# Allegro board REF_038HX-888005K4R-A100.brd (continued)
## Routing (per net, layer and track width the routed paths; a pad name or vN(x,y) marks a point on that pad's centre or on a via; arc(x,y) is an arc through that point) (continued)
N24642488: length 2.2
  BOTTOM w0.231: R53.2 93.8,160.77 94.63,161.6 K24.6
N24642490: length 2.2
  BOTTOM w0.231: R54.1 97.66,160.72 96.83,161.55 K24.5
N24780353: length 2.4
  BOTTOM w0.231: R131.1 K12.4
N24780370: length 2.4
  BOTTOM w0.231: R132.1 K12.5
N24787993: length 2.3
  BOTTOM w0.889: 94.1,260.04 CA21.1
  BOTTOM w1.524: K34.5 94.1,260.04
N24789529: length 7.4
  BOTTOM w0.889: 61.48,219.4 CA23.1
  BOTTOM w1.524: K36.8 K36.5 61.48,219.4
N24789779: length 2.3
  BOTTOM w0.889: 61.48,280.36 CA24.1
  BOTTOM w1.524: K37.5 61.48,280.36
N24793751: length 3.4
  TOP w0.231: RT3.1 RT5.1 UT1.3
N24793759: length 16.2
  TOP w0.231: UT1.4 149.59,241.68 v1(148.57,240.67)
  BOTTOM w0.231: v1(148.57,240.67) 152.89,240.67 157.11,244.89 159.52,244.89 v1(160.13,245.49)
N24793795: length 2.1
  TOP w0.231: UT1.6 RT7.2
N24793797: length 2.1
  TOP w0.231: UT1.5 RT8.2
N25306310: length 2.2
  BOTTOM w0.231: R102.2 93.8,185.29 94.63,184.46 K22.3
N25306320: length 2.2
  BOTTOM w0.231: K22.4 96.83,184.5 97.66,185.33 R103.1
N25306354: length 2.2
  BOTTOM w0.231: R104.2 83.17,195.33 82.34,194.5 K27.3
N25306364: length 2.2
  BOTTOM w0.231: K27.4 82.39,192.3 83.22,191.47 R105.1
N25330426: length 2.3
  BOTTOM w0.889: 61.08,239.72 CA29.1
  BOTTOM w1.524: K42.5 61.08,239.72
N25334489: length 2.3
  BOTTOM w0.889: 61.08,260.04 CA26.1
  BOTTOM w1.524: K39.5 61.08,260.04
N25337760: length 2.3
  BOTTOM w0.889: 77.79,260.04 CA34.1
  BOTTOM w1.524: K31.5 77.79,260.04
N25339188: length 2.3
  BOTTOM w0.889: 77.79,239.72 CA27.1
  BOTTOM w1.524: K40.5 77.79,239.72
N25362248: length 2.1
  BOTTOM w0.508: K33.2 R82.1
N25362250: length 2.1
  BOTTOM w0.508: K33.4 R117.1
N25362465: length 2.2
  BOTTOM w0.231: K11.3 144.88,272.51 145.71,271.68 R39.2
N25362471: length 2.2
  BOTTOM w0.231: R40.1 141.85,271.64 142.68,272.47 K11.4
N25362509: length 2.2
  BOTTOM w0.231: R38.1 141.85,265.52 142.68,264.69 K8.5
N25362552: length 2.2
  BOTTOM w0.231: K8.3 144.88,256 145.71,255.17 R35.2
N25362554: length 2.2
  BOTTOM w0.231: R36.1 141.85,255.13 142.68,255.96 K8.4
N25362556: length 2.2
  BOTTOM w0.231: K8.6 144.88,264.64 145.71,265.47 R37.2
N25362573: length 2.2
  BOTTOM w0.231: K11.6 144.88,281.15 145.71,281.98 R41.2
N25362575: length 2.2
  BOTTOM w0.231: R42.1 141.85,282.03 142.68,281.2 K11.5
N25362658: length 2.2
  BOTTOM w0.231: K3.5 173.16,297.71 172.33,298.54 R18.1
N25362663: length 2.2
  BOTTOM w0.231: R17.2 176.19,298.49 175.36,297.66 K3.6
N25362668: length 2.2
  BOTTOM w0.231: R16.1 172.33,288.15 173.16,288.98 K3.4
N25362670: length 2.2
  BOTTOM w0.231: R15.2 176.19,288.19 175.36,289.02 K3.3
N25362705: length 2.2
  BOTTOM w0.231: K1.5 173.16,281.2 172.33,282.03 R10.1
N25362707: length 2.2
  BOTTOM w0.231: K1.6 175.36,281.15 176.19,281.98 R9.2
N25362709: length 2.2
  BOTTOM w0.231: R8.1 172.33,271.64 173.16,272.47 K1.4
N25362711: length 2.2
  BOTTOM w0.231: K1.3 175.36,272.51 176.19,271.68 R7.2
N25362734: length 2.2
  BOTTOM w0.231: R11.2 176.19,255.17 175.36,256 K2.3
N25362739: length 2.2
  BOTTOM w0.231: K2.4 173.16,255.96 172.33,255.13 R12.1
N25362741: length 2.2
  BOTTOM w0.231: K4.5 157.92,297.71 157.09,298.54 R22.1
N25362761: length 2.2
  BOTTOM w0.231: K4.3 160.12,289.02 160.95,288.19 R19.2
N25362763: length 2.2
  BOTTOM w0.231: K4.4 157.92,288.98 157.09,288.15 R20.1
N25362765: length 2.2
  BOTTOM w0.231: R21.2 160.95,298.49 160.12,297.66 K4.6
N25362815: length 2.2
  BOTTOM w0.231: R26.1 157.09,265.52 157.92,264.69 K5.5
N25362863: length 2.2
  BOTTOM w0.231: K5.3 160.12,256 160.95,255.17 R23.2
N25362865: length 2.2
  BOTTOM w0.231: K5.4 157.92,255.96 157.09,255.13 R24.1
N25362867: length 2.2
  BOTTOM w0.231: R25.2 160.95,265.47 160.12,264.64 K5.6
N25363066: length 2.2
  BOTTOM w0.231: K16.3 129.64,256 130.47,255.17 R67.2
N25363068: length 2.2
  BOTTOM w0.231: R68.1 126.61,255.13 127.44,255.96 K16.4
N25363070: length 2.2
  BOTTOM w0.231: K16.5 127.44,264.69 126.61,265.52 R70.1
N25363072: length 2.2
  BOTTOM w0.231: K16.6 129.64,264.64 130.47,265.47 R69.2
N25363098: length 2.2
  BOTTOM w0.231: K17.3 129.64,272.51 130.47,271.68 R71.2
N25363100: length 2.2
  BOTTOM w0.231: R72.1 126.61,271.64 127.44,272.47 K17.4
N25363118: length 2.2
  BOTTOM w0.231: K17.5 127.44,281.2 126.61,282.03 R74.1
N25363120: length 2.2
  BOTTOM w0.231: R73.2 130.47,281.98 129.64,281.15 K17.6
N25363130: length 2.2
  BOTTOM w0.231: R75.2 130.47,288.19 129.64,289.02 K21.3
N25363148: length 2.2
  BOTTOM w0.231: R76.1 126.61,288.15 127.44,288.98 K21.4
N25363150: length 2.2
  BOTTOM w0.231: R78.1 126.61,298.54 127.44,297.71 K21.5
N25363152: length 2.2
  BOTTOM w0.231: K21.6 129.64,297.66 130.47,298.49 R77.2
N25363178: length 2.2
  BOTTOM w0.231: K29.3 114.4,272.51 115.23,271.68 R79.2
N25363180: length 2.2
  BOTTOM w0.231: K29.4 112.2,272.47 111.37,271.64 R80.1
N25363198: length 2.2
  BOTTOM w0.231: R14.1 172.33,265.52 173.16,264.69 K2.5
N25363200: length 2.2
  BOTTOM w0.231: R13.2 176.19,265.47 175.36,264.64 K2.6
N25363358: length 2.2
  BOTTOM w0.231: R43.2 115.23,281.98 114.4,281.15 K29.6
N25363360: length 2.2
  BOTTOM w0.231: R44.1 111.37,282.03 112.2,281.2 K29.5
N25363376: length 2.2
  BOTTOM w0.231: R63.2 115.23,288.19 114.4,289.02 K30.3
N25363378: length 2.2
  BOTTOM w0.231: R64.1 111.37,288.15 112.2,288.98 K30.4
N25363404: length 2.2
  BOTTOM w0.231: K30.5 112.2,297.71 111.37,298.54 R101.1
N25363406: length 2.2
  BOTTOM w0.231: K30.6 114.4,297.66 115.23,298.49 R100.2
N25363469: length 2.2
  BOTTOM w0.231: K6.5 157.92,281.2 157.09,282.03 R30.1
N25363533: length 2.2
  BOTTOM w0.231: R27.2 160.95,271.68 160.12,272.51 K6.3
N25363535: length 2.2
  BOTTOM w0.231: R28.1 157.09,271.64 157.92,272.47 K6.4
N25363537: length 2.2
  BOTTOM w0.231: K6.6 160.12,281.15 160.95,281.98 R29.2
N25363539: length 2.2
  BOTTOM w0.231: R34.1 141.85,298.54 142.68,297.71 K7.5
N25363555: length 2.2
  BOTTOM w0.231: R31.2 145.71,288.19 144.88,289.02 K7.3
N25363557: length 2.2
  BOTTOM w0.231: K7.4 142.68,288.98 141.85,288.15 R32.1
N25363559: length 2.2
  BOTTOM w0.231: R33.2 145.71,298.49 144.88,297.66 K7.6
N25363681: length 5.3
  BOTTOM w0.231: K18.4 100.66,244.92 100.25,245.33 R6.2 R5.1
N25363685: length 5.3
  BOTTOM w0.231: R133.1 R6.1 100.19,246.33 100.66,246.8 K18.5
N25363701: length 3.5
  BOTTOM w0.231: Y1.1 96.65,248.49 C5.1 R133.2
N25363703: length 6.1
  BOTTOM w0.231: Y1.3 94.14,244.15 95.12,243.17 C6.1 R5.2
N25363863: length 2.1
  BOTTOM w0.231: K13.5 R120.2
N25363865: length 2.1
  BOTTOM w0.231: K13.4 R119.2
N25363959: length 4.1
  BOTTOM w0.508: K28.5 R84.2 J5.1
N25363975: length 4.1
  BOTTOM w0.508: K28.4 R83.2 J4.1
N25462044: length 2.3
  BOTTOM w0.889: 52.36,260.04 CA37.1
  BOTTOM w1.524: K39.8 52.36,260.04
N25462912: length 2.3
  BOTTOM w0.889: 52.36,239.72 CA40.1
  BOTTOM w1.524: K42.8 52.36,239.72
N25463486: length 2.3
  BOTTOM w0.889: 69.07,239.72 CA28.1
  BOTTOM w1.524: K40.8 69.07,239.72
N25464528: length 2.3
  BOTTOM w0.889: 52.77,280.36 CA25.1
  BOTTOM w1.524: K37.8 52.77,280.36
N25465136: length 2.3
  BOTTOM w0.889: 85.38,260.04 CA22.1
  BOTTOM w1.524: K34.8 85.38,260.04
N25611014: length 12.4
  BOTTOM w0.231: UNK2R85.2 UNK2J1.2 UNK2S1_RST_N.2 260.23,198.73 260.23,201.39 260.9,202.06 UNK2K10.4
N25611025: length 2
  BOTTOM w0.231: UNK2J1.1 UNK2C7.1
N25611039: length 2.2
  BOTTOM w0.231: UNK2R55.2 163.17,210.57 162.34,209.74 UNK2K25.3
N25611040: length 2.2
  BOTTOM w0.231: UNK2R56.1 163.22,206.71 162.39,207.54 UNK2K25.4
N25611041: length 2.2
  BOTTOM w0.231: UNK2K25.6 153.71,209.74 152.88,210.57 UNK2R57.2
N25611042: length 2.2
  BOTTOM w0.231: UNK2R58.1 152.83,206.71 153.66,207.54 UNK2K25.5
N25611050: length 2.2
  BOTTOM w0.231: UNK2R59.2 178.41,195.33 177.58,194.5 UNK2K26.3
N25611051: length 2.2
  BOTTOM w0.231: UNK2R60.1 178.46,191.47 177.63,192.3 UNK2K26.4
N25611052: length 2.2
  BOTTOM w0.231: UNK2K26.6 168.95,194.5 168.12,195.33 UNK2R61.2
N25611053: length 2.2
  BOTTOM w0.231: UNK2K26.5 168.9,192.3 168.07,191.47 UNK2R62.1
N25611061: length 2.2
  BOTTOM w0.231: UNK2R66.1 152.83,191.47 153.66,192.3 UNK2K27.5
N25611062: length 2.2
  BOTTOM w0.231: UNK2K27.6 153.71,194.5 152.88,195.33 UNK2R65.2
N25611083: length 2.2
  BOTTOM w0.231: UNK2K22.6 174.63,175.83 173.8,175 UNK2R45.2
N25611084: length 2.2
  BOTTOM w0.231: UNK2R46.1 177.66,174.95 176.83,175.78 UNK2K22.5
N25611085: length 2.2
  BOTTOM w0.231: UNK2R47.2 189.04,171.07 189.87,170.24 UNK2K23.3
N25611086: length 2.2
  BOTTOM w0.231: UNK2R48.1 192.9,171.11 192.07,170.28 UNK2K23.4
N25611087: length 2.2
  BOTTOM w0.231: UNK2R49.2 189.04,160.77 189.87,161.6 UNK2K23.6
N25611088: length 2.2
  BOTTOM w0.231: UNK2K23.5 192.07,161.55 192.9,160.72 UNK2R50.1
N25611096: length 2.2
  BOTTOM w0.231: UNK2K24.3 174.63,170.24 173.8,171.07 UNK2R51.2
N25611097: length 2.2
  BOTTOM w0.231: UNK2K24.4 176.83,170.28 177.66,171.11 UNK2R52.1
N25611098: length 2.2
  BOTTOM w0.231: UNK2R53.2 173.8,160.77 174.63,161.6 UNK2K24.6
N25611099: length 2.2
  BOTTOM w0.231: UNK2K24.5 176.83,161.55 177.66,160.72 UNK2R54.1
N25611164: length 2.4
  BOTTOM w0.231: UNK2R131.1 UNK2K12.4
N25611166: length 2.4
  BOTTOM w0.231: UNK2R132.1 UNK2K12.5
N25611179: length 2.2
  BOTTOM w0.231: UNK2K22.3 174.63,184.46 173.8,185.29 UNK2R102.2
N25611180: length 2.2
  BOTTOM w0.231: UNK2R103.1 177.66,185.33 176.83,184.5 UNK2K22.4
N25611181: length 2.2
  BOTTOM w0.231: UNK2R104.2 163.17,195.33 162.34,194.5 UNK2K27.3
N25611182: length 2.2
  BOTTOM w0.231: UNK2R105.1 163.22,191.47 162.39,192.3 UNK2K27.4
N25611602: length 2.1
  BOTTOM w0.508: UNK2K33.2 UNK2R82.1
N25611603: length 2.1
  BOTTOM w0.508: UNK2K33.4 UNK2R117.1
N25611639: length 2.2
  BOTTOM w0.231: UNK2K11.3 209.64,289.02 210.47,288.19 UNK2R39.2
N25611640: length 2.2
  BOTTOM w0.231: UNK2R40.1 206.61,288.15 207.44,288.98 UNK2K11.4
N25611647: length 2.2
  BOTTOM w0.231: UNK2K8.5 222.94,264.69 222.11,265.52 UNK2R38.1
N25611655: length 2.2
  BOTTOM w0.231: UNK2K8.3 225.14,256 225.97,255.17 UNK2R35.2
N25611656: length 2.2
  BOTTOM w0.231: UNK2K8.4 222.94,255.96 222.11,255.13 UNK2R36.1
N25611657: length 2.2
  BOTTOM w0.231: UNK2K8.6 225.14,264.64 225.97,265.47 UNK2R37.2
N25611658: length 2.2
  BOTTOM w0.231: UNK2R41.2 210.47,298.49 209.64,297.66 UNK2K11.6
N25611659: length 2.2
  BOTTOM w0.231: UNK2R42.1 206.61,298.54 207.44,297.71 UNK2K11.5
N25611669: length 2.2
  BOTTOM w0.231: UNK2K3.5 268.66,297.71 267.83,298.54 UNK2R18.1
N25611670: length 2.2
  BOTTOM w0.231: UNK2K3.6 270.86,297.66 271.69,298.49 UNK2R17.2
N25611671: length 2.2
  BOTTOM w0.231: UNK2K3.4 268.66,288.98 267.83,288.15 UNK2R16.1
N25611672: length 2.2
  BOTTOM w0.231: UNK2R15.2 271.69,288.19 270.86,289.02 UNK2K3.3
N25611686: length 2.2
  BOTTOM w0.231: UNK2R10.1 267.83,265.52 268.66,264.69 UNK2K1.5
N25611687: length 2.2
  BOTTOM w0.231: UNK2K1.6 270.86,264.64 271.69,265.47 UNK2R9.2
N25611688: length 2.2
  BOTTOM w0.231: UNK2K1.4 268.66,255.96 267.83,255.13 UNK2R8.1
N25611689: length 2.2
  BOTTOM w0.231: UNK2K1.3 270.86,256 271.69,255.17 UNK2R7.2
N25611697: length 2.2
  BOTTOM w0.231: UNK2K2.3 270.86,272.51 271.69,271.68 UNK2R11.2
N25611700: length 2.2
  BOTTOM w0.231: UNK2R12.1 267.83,271.64 268.66,272.47 UNK2K2.4
N25611701: length 2.2
  BOTTOM w0.231: UNK2K4.5 253.42,297.71 252.59,298.54 UNK2R22.1
N25611709: length 2.2
  BOTTOM w0.231: UNK2R19.2 256.45,288.19 255.62,289.02 UNK2K4.3
N25611710: length 2.2
  BOTTOM w0.231: UNK2K4.4 253.42,288.98 252.59,288.15 UNK2R20.1
N25611711: length 2.2
  BOTTOM w0.231: UNK2R21.2 256.45,298.49 255.62,297.66 UNK2K4.6
N25611712: length 2.2
  BOTTOM w0.231: UNK2R26.1 252.59,265.52 253.42,264.69 UNK2K5.5
N25611720: length 2.2
  BOTTOM w0.231: UNK2R23.2 256.45,255.17 255.62,256 UNK2K5.3
N25611721: length 2.2
  BOTTOM w0.231: UNK2R24.1 252.59,255.13 253.42,255.96 UNK2K5.4
N25611722: length 2.2
  BOTTOM w0.231: UNK2K5.6 255.62,264.64 256.45,265.47 UNK2R25.2
N25611735: length 2.2
  BOTTOM w0.231: UNK2R67.2 210.47,271.68 209.64,272.51 UNK2K16.3
N25611736: length 2.2
  BOTTOM w0.231: UNK2K16.4 207.44,272.47 206.61,271.64 UNK2R68.1
N25611737: length 2.2
  BOTTOM w0.231: UNK2K16.5 207.44,281.2 206.61,282.03 UNK2R70.1
N25611738: length 2.2
  BOTTOM w0.231: UNK2R69.2 210.47,281.98 209.64,281.15 UNK2K16.6
N25611739: length 2.2
  BOTTOM w0.231: UNK2R71.2 210.73,255.17 209.9,256 UNK2K17.3
N25611740: length 2.2
  BOTTOM w0.231: UNK2R72.1 206.87,255.13 207.7,255.96 UNK2K17.4
N25611741: length 2.2
  BOTTOM w0.231: UNK2K17.5 207.7,264.69 206.87,265.52 UNK2R74.1
N25611742: length 2.2
  BOTTOM w0.231: UNK2R73.2 210.73,265.47 209.9,264.64 UNK2K17.6
N25611743: length 2.2
  BOTTOM w0.231: UNK2R75.2 195.23,288.19 194.4,289.02 UNK2K21.3
N25611744: length 2.2
  BOTTOM w0.231: UNK2K21.4 192.2,288.98 191.37,288.15 UNK2R76.1
N25611745: length 2.2
  BOTTOM w0.231: UNK2R78.1 191.37,298.54 192.2,297.71 UNK2K21.5
N25611746: length 2.2
  BOTTOM w0.231: UNK2K21.6 194.4,297.66 195.23,298.49 UNK2R77.2
N25611747: length 2.2
  BOTTOM w0.231: UNK2R79.2 195.23,271.68 194.4,272.51 UNK2K29.3
N25611748: length 2.2
  BOTTOM w0.231: UNK2K29.4 192.2,272.47 191.37,271.64 UNK2R80.1
N25611749: length 2.2
  BOTTOM w0.231: UNK2K2.5 268.66,281.2 267.83,282.03 UNK2R14.1
N25611750: length 2.2
  BOTTOM w0.231: UNK2K2.6 270.86,281.15 271.69,281.98 UNK2R13.2
N25611839: length 2.2
  BOTTOM w0.231: UNK2K29.6 194.4,281.15 195.23,281.98 UNK2R43.2
N25611840: length 2.2
  BOTTOM w0.231: UNK2R44.1 191.37,282.03 192.2,281.2 UNK2K29.5
N25611845: length 2.2
  BOTTOM w0.231: UNK2R63.2 195.23,255.17 194.4,256 UNK2K30.3
N25611846: length 2.2
  BOTTOM w0.231: UNK2K30.4 192.2,255.96 191.37,255.13 UNK2R64.1
N25611847: length 2.2
  BOTTOM w0.231: UNK2R101.1 191.37,265.52 192.2,264.69 UNK2K30.5
N25611848: length 2.2
  BOTTOM w0.231: UNK2K30.6 194.4,264.64 195.23,265.47 UNK2R100.2
N25611859: length 2.2
  BOTTOM w0.231: UNK2K6.5 253.42,281.2 252.59,282.03 UNK2R30.1
N25611867: length 2.2
  BOTTOM w0.231: UNK2K6.3 255.62,272.51 256.45,271.68 UNK2R27.2
N25611868: length 2.2
  BOTTOM w0.231: UNK2K6.4 253.42,272.47 252.59,271.64 UNK2R28.1
N25611869: length 2.2
  BOTTOM w0.231: UNK2K6.6 255.62,281.15 256.45,281.98 UNK2R29.2
N25611870: length 2.2
  BOTTOM w0.231: UNK2R34.1 237.35,265.52 238.18,264.69 UNK2K7.5
N25611878: length 2.2
  BOTTOM w0.231: UNK2K7.3 240.38,256 241.21,255.17 UNK2R31.2
N25611879: length 2.2
  BOTTOM w0.231: UNK2K7.4 238.18,255.96 237.35,255.13 UNK2R32.1
N25611880: length 2.2
  BOTTOM w0.231: UNK2R33.2 241.21,265.47 240.38,264.64 UNK2K7.6
N25611892: length 5.3
  BOTTOM w0.231: UNK2R5.1 UNK2R6.2 180.25,245.33 180.66,244.92 UNK2K18.4
N25611894: length 5.3
  BOTTOM w0.231: UNK2K18.5 180.66,246.8 180.19,246.33 UNK2R6.1 UNK2R133.1
N25611895: length 3.5
  BOTTOM w0.231: UNK2Y1.1 176.65,248.49 UNK2C5.1 UNK2R133.2
N25611896: length 6.1
  BOTTOM w0.231: UNK2R5.2 UNK2C6.1 175.12,243.17 174.14,244.15 UNK2Y1.3
N25611925: length 2.1
  BOTTOM w0.231: UNK2R120.2 UNK2K13.5
N25611926: length 2.1
  BOTTOM w0.231: UNK2R119.2 UNK2K13.4
N25611946: length 4.1
  BOTTOM w0.508: UNK2J5.1 UNK2R84.2 UNK2K28.5
N25611950: length 4.1
  BOTTOM w0.508: UNK2J4.1 UNK2R83.2 UNK2K28.4
N25615773: length 2
  BOTTOM w0.231: UNK2R89.1 UNK2J2.1
N25615777: length 2
  BOTTOM w0.231: UNK2R96.1 UNK2J3.1
N25615779: length 2
  BOTTOM w0.231: UNK2J3.3 UNK2R93.1
N25615786: length 2.5
  BOTTOM w0.231: UNK2U1.7 UNK2R90.1
N25615811: length 15.6
  BOTTOM w0.231: UNK2U1.3 263.07,176.29 263.07,181.66 262.21,182.53 UNK2J2.2
N25615820: length 2.5
  BOTTOM w0.231: UNK2U2.7 UNK2R97.1
N25615847: length 14.2
  BOTTOM w0.231: UNK2J3.2 275.1,180.92 275.1,172.22 275.84,171.48 UNK2U2.3
N25615858: length 2
  BOTTOM w0.231: UNK2J2.3 UNK2R86.1
N25616611: length 2.3
  BOTTOM w0.889: 44.77,280.36 UNK2CA21.1
  BOTTOM w1.524: UNK2K34.5 44.77,280.36
N25616617: length 7.4
  BOTTOM w0.889: 28.46,219.4 UNK2CA23.1
  BOTTOM w1.524: 28.46,219.4 UNK2K36.5 UNK2K36.8
N25616622: length 2.3
  BOTTOM w0.889: 28.46,280.36 UNK2CA24.1
  BOTTOM w1.524: UNK2K37.5 28.46,280.36
N25616748: length 2.3
  BOTTOM w0.889: 28.46,239.72 UNK2CA29.1
  BOTTOM w1.524: UNK2K42.5 28.46,239.72
N25616755: length 2.3
  BOTTOM w0.889: 28.46,260.04 UNK2CA26.1
  BOTTOM w1.524: UNK2K39.5 28.46,260.04
N25616834: length 2.3
  BOTTOM w0.889: 44.77,260.04 UNK2CA34.1
  BOTTOM w1.524: UNK2K31.5 44.77,260.04
N25616842: length 2.3
  BOTTOM w0.889: 44.77,239.72 UNK2CA27.1
  BOTTOM w1.524: UNK2K40.5 44.77,239.72
N25616987: length 2.3
  BOTTOM w0.889: 19.75,260.04 UNK2CA37.1
  BOTTOM w1.524: UNK2K39.8 19.75,260.04
N25616993: length 2.3
  BOTTOM w0.889: 19.75,239.72 UNK2CA40.1
  BOTTOM w1.524: UNK2K42.8 19.75,239.72
N25616997: length 2.3
  BOTTOM w0.889: 36.05,239.72 UNK2CA28.1
  BOTTOM w1.524: UNK2K40.8 36.05,239.72
N25616999: length 2.3
  BOTTOM w0.889: 19.75,280.36 UNK2CA25.1
  BOTTOM w1.524: UNK2K37.8 19.75,280.36
N25617005: length 2.3
  BOTTOM w0.889: 36.05,280.36 UNK2CA22.1
  BOTTOM w1.524: UNK2K34.8 36.05,280.36
N25619537: length 3.4
  TOP w0.231: UNK2UT1.3 UNK2RT5.1 UNK2RT3.1
N25619539: length 16.2
  TOP w0.231: UNK2UT1.4 229.92,241.68 228.91,240.67 v1(228.57,240.67)
  BOTTOM w0.231: v1(228.57,240.67) 232.89,240.67 237.11,244.89 239.52,244.89 v1(240.13,245.49)
N25619557: length 2.1
  TOP w0.231: UNK2UT1.6 UNK2RT7.2
N25619558: length 2.1
  TOP w0.231: UNK2UT1.5 UNK2RT8.2

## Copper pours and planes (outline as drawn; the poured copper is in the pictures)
AGND on L03_SIGNAL (solid shape): 117.13,146.05 117.24,146.07 117.31,145.97 117.31,144.6 72.07,99.36 71.96,99.34 71.89,99.44 71.89,100.81
AGND on L03_SIGNAL (solid shape): 179.49,111.78 179.58,111.71 179.56,111.6 179.25,111.29 163,111.29 162.9,111.36 162.93,111.47 163.23,111.78
AGND on L03_SIGNAL (solid shape): 103.18,141.65 103.29,141.68 103.35,141.58 103.35,140.65 67.62,104.93 67.51,104.91 67.45,105 67.45,105.29 94.62,132.45 94.62,133.09
AGND on L03_SIGNAL (solid shape): 189.61,153.97 189.72,153.99 189.78,153.89 189.78,139.1 182.05,131.36 182.05,114.09 181.97,114.01 181.86,113.99 181.8,114.09 181.8,132.31 183.01,133.52 183.01,135.26 189.43,141.67 189.43,153.78
AGND on L03_SIGNAL (solid shape): 193.23,132.29 193.34,132.31 193.4,132.22 193.4,127.86 190.06,124.52 190.06,102.97 189.38,102.29 187.91,102.29 187.82,102.35 187.84,102.46 188.75,103.37 188.75,125.95 192.95,130.15 192.95,132.02
AGND on L03_SIGNAL (solid shape): 120.62,42.56 120.71,42.5 120.69,42.39 117.23,38.93 117.2,38.93 116.91,38.91 116.64,38.8 116.54,38.79 116.48,38.88 116.48,41.56 117.49,42.56
AGND on L03_SIGNAL (solid shape): 125.32,62.51 125.42,62.45 125.39,62.34 122.31,59.25 122.28,59.25 121.96,59.23 121.68,59.08 121.57,59.07 121.51,59.16 121.51,61.71 122.32,62.51
AGND on L03_SIGNAL (solid shape): 196.93,124.65 197.04,124.67 197.11,124.59 197.47,124.23 197.47,103.11 197.35,102.99 196.27,102.99 195.83,103.44 195.83,115.27 195.09,116.01 193.81,116.01 193.24,115.44 193.24,100.66 192.85,100.26 192.47,100.26 192.38,100.33 192.4,100.44 192.9,100.94 192.9,120.62
AGND on L03_SIGNAL (solid shape): 111.34,158.93 111.34,152.71 111.88,152.16 113.08,152.16 113.23,152.3 113.34,152.33 113.4,152.23 113.4,145.53 70.16,102.3 70.05,102.28 69.99,102.37 69.99,103.17 106.92,140.1 106.92,158.62 107.23,158.93 107.76,158.93 108.04,158.65 108.04,146.5 108.65,145.89 109.78,145.89 110.38,146.48 110.38,158.94 110.53,159.1 111.17,159.1
AGND on L03_SIGNAL (solid shape): 116.53,43.28 116.63,43.22 116.6,43.11 115.48,41.98 115.48,37.7 115.09,37.31 112.67,37.31 112.57,37.37 112.6,37.48 112.82,37.81 112.86,38.19 112.86,38.22 114.15,39.51 114.15,41.89 115.54,43.28
AGND on L03_SIGNAL (solid shape): 139.4,140.83 139.46,140.74 139.46,133.95 110.13,104.62 91.45,104.62 91.36,104.68 91.38,104.79 91.57,104.98 102.52,104.98 138.05,140.5 138.05,140.69 138.1,140.78 138.2,140.78 138.76,140.63 139.3,140.82
AGND on L03_SIGNAL (solid shape): 62.46,70.86 62.57,70.88 62.63,70.79 62.63,70.69 58.19,66.25 58.19,63.71 53.73,59.25 53.7,59.25 52.83,58.74 53.09,57.76 53.12,57.65 53.02,57.58 50.43,57.58 50.43,58.83
AGND on L03_SIGNAL (solid shape): 113.7,56.35 113.79,56.3 113.8,56.21 113.9,55.38 114.66,55.05 114.69,55.05 118.89,50.84 118.91,50.73 118.82,50.67 115.41,50.67 110.32,55.76 110.32,55.79 110.32,56 110.26,56.21 110.27,56.3 110.36,56.35
AGND on L03_SIGNAL (solid shape): 118.78,56.35 118.87,56.3 118.88,56.21 118.98,55.38 119.74,55.05 119.77,55.05 123.34,51.48 123.36,51.37 123.27,51.3 119.86,51.3 115.4,55.76 115.4,55.79 115.4,56 115.34,56.21 115.35,56.3 115.44,56.35
AGND on L03_SIGNAL (solid shape): 50.45,36.37 50.54,36.3 50.52,36.19 50.23,35.51 50.59,34.87 50.62,34.85 50.62,34.72 50.51,34.61 48.73,34.61 48.15,34.04 46.81,35.38 46.81,35.41 46.78,35.84 46.54,36.19 46.51,36.3 46.61,36.37
AGND on L03_SIGNAL (solid shape): 104.63,38.89 106.34,38.89 106.37,38.85 106.4,38.78 106.37,38.71 106.11,38.09 106.38,37.48 106.41,37.37 106.31,37.31 102.51,37.31 102.41,37.37 102.44,37.48 102.66,37.83 102.69,38.25 102.69,38.28 103.96,39.55
AGND on L03_SIGNAL (solid shape): 57.86,43.31 57.95,43.25 57.93,43.14 53.73,38.93 53.7,38.93 52.87,38.49 52.98,37.55 53,37.44 52.9,37.38 49.24,37.38 49.14,37.44 49.16,37.55 49.33,37.85 49.36,38.19 49.36,38.22 54.45,43.31
AGND on L03_SIGNAL (solid shape): 98.64,36.3 98.73,36.24 98.71,36.13 98.58,35.18 99.42,34.73 99.45,34.73 105.57,28.6 105.59,28.49 105.5,28.43 102.09,28.43 95.08,35.44 95.08,35.47 95.05,35.82 94.87,36.13 94.85,36.24 94.94,36.3
AGND on L03_SIGNAL (solid shape): 103.72,36.3 103.81,36.24 103.79,36.13 103.66,35.18 104.5,34.73 104.53,34.73 110.02,29.24 110.04,29.13 109.95,29.07 106.54,29.07 100.16,35.44 100.16,35.47 100.13,35.82 99.95,36.13 99.93,36.24 100.02,36.3
AGND on L03_SIGNAL (solid shape): 108.8,36.3 108.89,36.24 108.87,36.13 108.74,35.18 109.58,34.73 109.61,34.73 114.46,29.87 114.48,29.76 114.39,29.7 110.98,29.7 105.24,35.44 105.24,35.47 105.21,35.82 105.03,36.13 105.01,36.24 105.1,36.3
AGND on L03_SIGNAL (solid shape): 113.88,36.3 113.97,36.24 113.95,36.13 113.82,35.18 114.66,34.73 114.69,34.73 118.91,30.51 118.93,30.4 118.84,30.34 115.43,30.34 110.32,35.44 110.32,35.47 110.29,35.82 110.11,36.13 110.09,36.24 110.18,36.3
AGND on L03_SIGNAL (solid shape): 136.79,69.13 136.79,65.02 136.63,64.87 116.47,64.87 115.57,63.96 115.57,59.25 116.28,58.54 116.28,58.51 117.7,57.83 117.02,59.25 116.99,59.25 116.57,59.67 116.57,63.54 116.89,63.86 137.05,63.86 137.39,64.2 137.5,64.22 137.56,64.13 137.56,63.97 137.11,63.52 121.9,63.52 120.5,62.12 120.5,58.06 119.8,57.36 113.94,57.36 113.89,57.39 113.91,57.45 113.91,65.34 116.64,68.08 116.77,68.08 116.82,68.04 116.81,67.99 116.48,67.66 116.48,66.51 117.1,65.89 134.98,65.89 135.72,66.64 135.72,69.28 135.79,69.35 136.57,69.35
AGND on L03_SIGNAL (solid shape): outline of 145 points within 143.65,94.94 192.85,168.97
AGND on L03_SIGNAL (solid shape): outline of 175 points within 143.01,96.61 185.33,160.07
AGND on L03_SIGNAL (solid shape): outline of 379 points within 120.29,51.94 138.83,62.27
AGND on L03_SIGNAL (solid shape): outline of 521 points within 115.16,31.04 155.03,55.1
AGND on TOP: 117.64,201.55 138.41,201.55 139.91,200.04 150.82,200.04 151.61,200.83 151.61,211.45 152.98,212.81 188.04,212.81 190.66,210.19 192.11,210.19 192.27,210.03 192.84,210.03 193.29,209.58 193.29,206.43 193.31,206.41 193.31,205.58 193.5,205.38 196.12,205.38 197.04,204.46 197.04,201.85 197.24,201.65 218.14,201.65 221.25,198.54 221.25,193.49 253.7,161.04 253.7,158.15 275.54,136.3 275.54,130.68 278.49,127.74 278.49,83.82 277.39,82.72 159.52,82.72 153.24,89 153.24,103.5 128.21,128.53 64.76,128.53 61.32,131.98 61.32,164.13 70.12,172.92 70.12,216.37 72.88,219.13 83.81,219.13 90.16,212.79 110.88,212.79 113.24,210.42 113.24,205.95 113.71,205.48 116.16,205.48 117.22,204.41 117.22,201.97
AGND on BOTTOM: 172.7,251.71 200.82,251.71 202.21,250.31 202.21,240.1 205.3,237.01 205.3,234.19 208.12,231.36 208.12,226.61 207.58,226.06 201.01,226.06 187.82,239.25 174.67,239.25 171.34,242.58 171.34,250.35
AGND on BOTTOM: 92.7,251.71 120.82,251.71 122.21,250.31 122.21,240.1 125.3,237.01 125.3,234.19 128.12,231.36 128.12,226.61 127.58,226.06 121.01,226.06 107.82,239.25 94.67,239.25 91.34,242.58 91.34,250.35
AGND on L02_GND: 1.02,1.02 1.02,428.24 61.42,428.24 72.66,422.59 83.9,428.24 208.74,428.24 219.98,422.59 231.22,428.24 291.62,428.24 291.62,1.02 157.55,1.02 156.96,1.78 156.12,2.68 155.21,3.5 154.23,4.23 153.19,4.87 152.1,5.43 150.96,5.88 149.79,6.24 148.6,6.49 147.38,6.64 146.16,6.68 144.94,6.61 143.73,6.44 142.54,6.16 141.38,5.78 140.25,5.3 139.17,4.72 138.15,4.05 137.19,3.3 136.3,2.46 135.48,1.55 135.08,1.02
AGND on L03_SIGNAL: 156.96,1.78 156.12,2.68 155.21,3.5 154.23,4.23 153.19,4.87 152.1,5.43 150.96,5.88 149.79,6.24 148.6,6.49 147.38,6.64 146.16,6.68 144.94,6.61 143.73,6.44 142.54,6.16 141.38,5.78 140.25,5.3 139.17,4.72 138.15,4.05 137.19,3.3 136.3,2.46 135.48,1.55 135.08,1.02 1.02,1.02 1.02,428.24 61.42,428.24 72.66,422.59 83.9,428.24 208.74,428.24 219.98,422.59 231.22,428.24 291.62,428.24 291.62,1.02 157.55,1.02 ; 86 cut-outs
AGND on L04_GND, L05_SIGNAL, L06_GND, L08_GND, L10_GND, L15_GND, L17_GND, L19_GND, L21_GND, L22_SIGNAL, L23_GND: 156.96,1.78 156.12,2.68 155.21,3.5 154.23,4.23 153.19,4.87 152.1,5.43 150.96,5.88 149.79,6.24 148.6,6.49 147.38,6.64 146.16,6.68 144.94,6.61 143.73,6.44 142.54,6.16 141.38,5.78 140.25,5.3 139.17,4.72 138.15,4.05 137.19,3.3 136.3,2.46 135.48,1.55 135.08,1.02 1.02,1.02 1.02,428.24 61.42,428.24 72.66,422.59 83.9,428.24 208.74,428.24 219.98,422.59 231.22,428.24 291.62,428.24 291.62,1.02 157.55,1.02
AGND on L07_SIGNAL: 156.96,1.78 156.12,2.68 155.21,3.5 154.23,4.23 153.19,4.87 152.1,5.43 150.96,5.88 149.79,6.24 148.6,6.49 147.38,6.64 146.16,6.68 144.94,6.61 143.73,6.44 142.54,6.16 141.38,5.78 140.25,5.3 139.17,4.72 138.15,4.05 137.19,3.3 136.3,2.46 135.48,1.55 135.08,1.02 1.02,1.02 1.02,428.24 61.42,428.24 72.66,422.59 83.9,428.24 208.74,428.24 219.98,422.59 231.22,428.24 291.62,428.24 291.62,1.02 157.55,1.02 ; 97 cut-outs
AGND on L09_POWER: 156.96,1.78 156.12,2.68 155.21,3.5 154.23,4.23 153.19,4.87 152.1,5.43 150.96,5.88 149.79,6.24 148.6,6.49 147.38,6.64 146.16,6.68 144.94,6.61 143.73,6.44 142.54,6.16 141.38,5.78 140.25,5.3 139.17,4.72 138.15,4.05 137.19,3.3 136.3,2.46 135.48,1.55 135.08,1.02 1.02,1.02 1.02,428.24 61.42,428.24 72.66,422.59 83.9,428.24 208.74,428.24 219.98,422.59 231.22,428.24 291.62,428.24 291.62,1.02 157.55,1.02 ; 1 cut-out
AGND on L11_POWER: 156.96,1.78 156.12,2.68 155.21,3.5 154.23,4.23 153.19,4.87 152.1,5.43 150.96,5.88 149.79,6.24 148.6,6.49 147.38,6.64 146.16,6.68 144.94,6.61 143.73,6.44 142.54,6.16 141.38,5.78 140.25,5.3 139.17,4.72 138.15,4.05 137.19,3.3 136.3,2.46 135.48,1.55 135.08,1.02 1.02,1.02 1.02,428.24 61.42,428.24 72.66,422.59 83.9,428.24 208.74,428.24 219.98,422.59 231.22,428.24 291.62,428.24 291.62,1.02 157.55,1.02 ; 1 cut-out
AGND on L13_CBIT: 156.96,1.78 156.12,2.68 155.21,3.5 154.23,4.23 153.19,4.87 152.1,5.43 150.96,5.88 149.79,6.24 148.6,6.49 147.38,6.64 146.16,6.68 144.94,6.61 143.73,6.44 142.54,6.16 141.38,5.78 140.25,5.3 139.17,4.72 138.15,4.05 137.19,3.3 136.3,2.46 135.48,1.55 135.08,1.02 1.02,1.02 1.02,428.24 61.42,428.24 72.66,422.59 83.9,428.24 208.74,428.24 219.98,422.59 231.22,428.24 291.62,428.24 291.62,1.02 157.55,1.02 ; 10 cut-outs
AGND on L14_POWER: 156.96,1.78 156.12,2.68 155.21,3.5 154.23,4.23 153.19,4.87 152.1,5.43 150.96,5.88 149.79,6.24 148.6,6.49 147.38,6.64 146.16,6.68 144.94,6.61 143.73,6.44 142.54,6.16 141.38,5.78 140.25,5.3 139.17,4.72 138.15,4.05 137.19,3.3 136.3,2.46 135.48,1.55 135.08,1.02 1.02,1.02 1.02,428.24 61.42,428.24 72.66,422.59 83.9,428.24 208.74,428.24 219.98,422.59 231.22,428.24 291.62,428.24 291.62,1.02 157.55,1.02 ; 1 cut-out
AGND on L16_POWER: 208.24,427.23 219.98,421.57 231.72,427.23 290.61,427.23 290.61,2.03 158.05,2.03 157.73,2.44 156.83,3.41 155.85,4.28 154.8,5.07 153.69,5.76 152.52,6.35 151.3,6.84 150.05,7.22 148.76,7.49 147.46,7.65 146.15,7.69 144.84,7.62 143.54,7.44 142.27,7.14 141.02,6.73 139.81,6.22 138.66,5.6 137.56,4.88 136.53,4.07 135.57,3.17 134.69,2.2 134.57,2.03 2.03,2.03 2.03,427.23 60.92,427.23 72.66,421.57 84.4,427.23 ; 1 cut-out
AGND on L18_POWER: 156.96,1.78 156.12,2.68 155.21,3.5 154.23,4.23 153.19,4.87 152.1,5.43 150.96,5.88 149.79,6.24 148.6,6.49 147.38,6.64 146.16,6.68 144.94,6.61 143.73,6.44 142.54,6.16 141.38,5.78 140.25,5.3 139.17,4.72 138.15,4.05 137.19,3.3 136.3,2.46 135.48,1.55 135.08,1.02 1.02,1.02 1.02,428.24 61.42,428.24 72.66,422.59 83.9,428.24 208.74,428.24 219.98,422.59 231.22,428.24 291.62,428.24 291.62,1.02 157.55,1.02 ; 1 cut-out
AGND on L20_SIGNAL: 156.96,1.78 156.12,2.68 155.21,3.5 154.23,4.23 153.19,4.87 152.1,5.43 150.96,5.88 149.79,6.24 148.6,6.49 147.38,6.64 146.16,6.68 144.94,6.61 143.73,6.44 142.54,6.16 141.38,5.78 140.25,5.3 139.17,4.72 138.15,4.05 137.19,3.3 136.3,2.46 135.48,1.55 135.08,1.02 1.02,1.02 1.02,428.24 61.42,428.24 72.66,422.59 83.9,428.24 208.74,428.24 219.98,422.59 231.22,428.24 291.62,428.24 291.62,1.02 157.55,1.02 ; 1 cut-out
CSDPS225P1 on L18_POWER: 110.47,192.72 110.47,184.65 113.07,182.05 131.9,182.05 138.58,188.73 138.58,227.98 140.98,230.38 140.98,250.52 137.67,253.83 104.62,253.83 101.97,256.48 101.97,265.18 139.73,302.94 139.73,331.81 137.11,334.43 128.97,334.43 128.15,333.61 128.15,329.2 128.8,328.55 130.75,328.55 131.79,327.51 131.79,308.25 90.51,266.97 90.51,249.91 98.49,241.93 123.05,241.93 123.78,241.21 123.78,234.24 130.29,227.73 130.29,193.85 126.41,189.98 121.41,189.98 120.28,191.1 120.28,206.27 119.37,207.18 113.34,207.18 112.58,206.42 112.58,194.83
CSDPS225P3 on L11_POWER: 129.04,223.04 128.71,223.37 128.71,229.99 125.73,232.97 125.73,252.8 121.38,257.15 74.32,257.15 72.65,258.82 72.65,292.39 87.01,306.76 103.62,306.76 115.29,318.43 115.29,333.25 116.44,334.39 125.43,334.39 125.99,333.83 125.99,329.45 125.52,328.98 122.09,328.98 121.41,328.3 121.41,313.43 107.19,299.21 92,299.21 79.22,286.43 79.22,270.32 81.94,267.6 125.68,267.6 133.27,260.01 133.27,224.19 132.12,223.04
CSDPS225P5 on L14_POWER: 131.99,223.39 131.99,228.26 138.53,234.81 138.53,237.29 138.89,237.65 138.89,249.27 136.09,252.07 84.11,252.07 82.18,254.01 82.18,289.81 95.97,303.6 111.34,303.6 128.83,321.09 128.83,333.46 127.88,334.41 119.12,334.41 118.02,333.31 118.02,329.36 118.65,328.73 120.11,328.73 120.56,328.28 120.56,325.03 108.5,312.97 91.42,312.97 74.85,296.4 74.85,238.04 76.28,236.61 84.36,236.61 94.72,246.96 129.8,246.96 132.84,243.93 132.84,239.71 131.35,238.22 128.55,238.22 127.87,237.54 127.87,223.27 128.09,223.05 131.64,223.05
CSDPS225P7 on L16_POWER: 123.05,206.83 123.05,194.83 116.31,188.09 88.7,188.09 67,209.79 67,290.16 94.03,317.19 103.69,317.19 111.14,324.64 111.14,327.95 111.71,328.53 115.2,328.53 116.27,329.61 116.27,333.51 115.35,334.43 103.58,334.43 102.75,333.59 102.75,327.23 99.62,324.11 89.48,324.11 58.2,292.83 58.2,207.48 82.01,183.67 120.31,183.67 128.34,191.7 128.34,206.65 127.74,207.25 123.47,207.25
CSDPS225P9 on L09_POWER: 121.38,222.53 121.88,223.04 122.63,223.04 122.95,223.35 122.95,224.1 123.82,224.97 123.82,239.12 120.61,242.32 81.37,242.32 71.97,251.72 64.85,251.72 57.16,259.4 57.16,284.55 86.35,313.75 114.1,313.75 118.76,318.41 118.76,332.99 117.74,334.01 108.59,334.01 107.86,333.27 107.86,329.36 108.59,328.63 109.92,328.63 110.42,328.13 110.42,324.53 105.64,319.75 81.17,319.75 50.57,289.15 50.57,255.24 60.06,245.76 83.29,222.53
CSDPS225P11 on L14_POWER: 62.72,318 79.13,334.4 105.06,334.4 106.03,333.43 106.03,329.54 105.26,328.77 101.76,328.77 101.02,328.03 101.02,325.51 97.66,322.16 83.34,322.16 72.41,311.23 72.41,236.39 75.19,233.61 82.73,233.61 95.21,246.09 127.02,246.09 130.65,242.45 130.65,239.44 130.34,239.13 127.94,239.13 126.96,238.15 126.96,233.88 126.5,233.42 126.5,223.38 126.13,223.01 122.9,223.01 122.47,223.44 122.47,238.19 121.51,239.15 110.15,239.15 109.14,240.17 102.42,240.17 88.44,226.19 66.02,226.19 62.72,229.48
CSDPS225P13 on L09_POWER: 124.63,223.14 124.63,236.46 125.53,237.37 130.81,237.37 132.02,236.15 132.02,216.8 132.8,216.02 149.6,216.02 151.99,213.63 151.99,200.99 150.35,199.35 140.2,199.35 139.83,198.98 139.83,192.34 138.22,190.73 111.66,190.73 110.59,191.79 110.59,196.73 106.48,200.85 65.79,200.85 50.72,215.92 50.72,227.1 39.78,238.04 39.78,244.62 35.88,248.52 35.88,291.77 83.47,339.36 99.81,339.36 100.71,338.46 100.71,329.59 100.07,328.95 84.65,328.95 46.96,291.27 46.96,253.63 53.58,247.01 53.58,239.31 76.06,216.84 100.09,216.84 103,219.74 121.23,219.74
CSDPS229P1 on L18_POWER: 190.47,192.72 190.47,184.65 193.07,182.05 211.9,182.05 218.58,188.73 218.58,227.98 220.98,230.38 220.98,250.52 217.67,253.83 176.82,253.83 157.35,234.36 157.35,193.13 142.49,178.27 83.18,178.27 48.81,212.65 48.81,299.34 65.62,316.15 65.62,331.58 62.88,334.33 55.17,334.33 54.56,333.72 54.56,329.37 55.17,328.76 57.08,328.76 57.83,328.01 57.83,321.67 41.58,305.42 41.58,206.23 78.31,169.5 145.5,169.5 164.81,188.81 164.81,225.76 180.99,241.93 203.05,241.93 203.78,241.21 203.78,234.24 210.29,227.73 210.29,193.85 206.41,189.98 201.41,189.98 200.28,191.1 200.28,206.27 199.37,207.18 193.34,207.18 192.58,206.42 192.58,194.83
CSDPS229P3 on L11_POWER: 209.04,223.04 208.71,223.37 208.71,229.99 205.73,232.97 205.73,240.75 204.73,241.76 174.81,241.76 163.88,230.83 163.88,189.03 153.04,178.19 72.98,178.19 39.01,212.16 39.01,311.41 41.78,314.18 41.78,333.48 42.7,334.4 52.17,334.4 52.78,333.79 52.78,329.69 51.78,328.7 48.21,328.7 47.67,328.16 47.67,309.46 46.2,307.99 46.2,214.87 74.98,186.09 150.92,186.09 157.43,192.6 157.43,234.59 170.69,247.85 211.27,247.85 213.27,245.86 213.27,224.19 212.12,223.04
CSDPS229P5 on L14_POWER: 60.94,164.67 53.21,172.4 53.21,176.59 40.92,188.87 40.92,315.52 47,321.6 47,328 46.37,328.63 45.3,328.63 44.66,329.26 44.66,333.4 45.6,334.33 54.51,334.33 54.99,333.85 54.99,316.69 51.42,313.11 51.42,200.62 73.76,178.28 142.13,178.28 153.39,189.54 153.39,243.89 165.71,256.21 213.52,256.21 218.89,250.85 218.89,235.17 211.99,228.26 211.99,223.39 211.64,223.05 208.09,223.05 207.87,223.27 207.87,237.54 208.55,238.22 211.35,238.22 212.84,239.71 212.84,243.93 209.8,246.96 172.08,246.96 164.82,239.7 164.82,178.08 151.41,164.67
CSDPS229P7 on L16_POWER: 203.05,206.83 203.05,198.04 172.47,167.46 58.65,167.46 48.51,177.6 48.51,194.52 33.17,209.87 33.17,309.73 37.52,314.08 37.52,328.13 37.94,328.56 41.31,328.56 42.59,329.84 42.59,333.78 41.97,334.4 30.44,334.4 29.14,333.1 29.14,315.61 25.14,311.61 25.14,201.03 38.62,187.56 38.62,172.11 51.27,159.46 173.49,159.46 208.33,194.31 208.33,206.65 207.74,207.25 203.47,207.25
CSDPS229P9 on L09_POWER: 182.79,222.53 201.38,222.53 201.88,223.04 202.63,223.04 202.95,223.35 202.95,224.1 203.82,224.97 203.82,241.11 202.38,242.55 176.3,242.55 169.46,235.7 169.46,185.78 164.53,180.86 69.91,180.86 69.06,180.01 61.1,180.01 60.38,180.73 49.12,180.73 46.96,182.9 46.96,192.13 41.13,197.97 41.13,225.55 28.9,237.78 26.27,237.78 23.54,240.51 23.54,300.76 45.25,322.46 45.25,332.84 43.76,334.33 34.93,334.33 34.13,333.53 34.13,329.31 34.82,328.62 36.15,328.62 36.69,328.08 36.69,323.47 16.24,303.03 16.24,236.32 21.6,230.96 26.87,230.96 33.55,224.27 33.55,172.42 36.37,169.6 89.59,169.6 91.78,171.79 166.28,171.79 177.95,183.47 177.95,217.7
CSDPS229P11 on L14_POWER: 44.91,150.73 27.91,167.73 27.91,294.29 18.38,303.81 18.38,333.28 19.58,334.48 31.29,334.48 32.21,333.57 32.21,329.39 31.62,328.8 27.89,328.8 27.32,328.24 27.32,320.31 39.34,308.29 39.34,171.92 51.08,160.17 151.57,160.17 170.97,179.57 170.97,241.85 175.21,246.09 207.02,246.09 210.65,242.45 210.65,239.44 210.34,239.13 207.94,239.13 206.96,238.15 206.96,233.88 206.68,233.6 206.68,223.57 206.17,223.06 203.13,223.06 202.49,223.71 202.49,236.19 199.52,239.15 190.15,239.15 189.14,240.17 182.42,240.17 179.88,237.63 179.88,171.32 159.29,150.73
CSDPS229P13 on L09_POWER: 204.63,236.46 205.53,237.37 210.81,237.37 212.02,236.15 212.02,216.8 212.8,216.02 229.6,216.02 231.99,213.63 231.99,200.99 230.35,199.35 220.2,199.35 219.83,198.98 219.83,192.34 218.21,190.73 216.28,190.73 172.49,146.94 105.87,146.94 101.65,151.15 24.7,151.15 12.95,162.9 12.95,218.38 3.86,227.46 3.86,308 10.67,314.81 10.67,338.32 11.8,339.45 26.25,339.45 26.84,338.86 26.84,329.65 25.78,328.59 20.3,328.59 18.84,327.13 18.84,311.05 12.61,304.82 12.61,234.2 20.72,226.09 27.58,226.09 29.91,223.75 29.91,217 28.66,215.75 28.66,171.95 35.34,165.28 163.53,165.28 190.94,192.69 190.94,196.37 191.5,196.93 191.5,198.85 189.97,200.39 182.33,200.39 181.37,201.34 181.37,215.5 183.29,217.41 187.8,217.41 190.17,219.78 202.06,219.78 204.63,222.35
CSDPS425P1 on L09_POWER: 147.23,217.08 149.26,219.1 149.26,227.46 153.44,231.65 153.44,251.46 137.7,267.2 71.16,267.2 68.96,269.4 68.96,276.18 96.09,303.32 118.58,303.32 136.37,321.1 136.37,344.49 134.1,346.76 129.5,346.76 128.31,345.57 128.31,339.9 129.42,338.78 130.7,338.78 131.05,338.44 131.05,325.44 114.68,309.08 90.75,309.08 58.34,276.66 58.34,259.27 61.3,256.3 122.72,256.3 130.99,248.03 130.99,239.51 133,237.5 133,220.62 133.93,219.69 133.93,218.28 135.12,217.08
CSDPS425P3 on L20_SIGNAL: 125.33,147.12 84.72,187.73 84.72,269.93 90,275.21 90,293.29 109.13,312.42 128.12,312.42 133.25,317.55 133.25,343.64 132.32,344.57 124.3,344.57 123.3,343.57 123.3,339.41 123.83,338.88 125.27,338.88 126.05,338.09 126.05,326.44 121.68,322.08 107.32,322.08 84.17,298.93 84.17,280.79 78.64,275.26 78.64,175.33 117.17,136.8 117.17,131.43 118.69,129.91 123.89,129.91 125.33,131.35
CSDPS425P7 on L11_POWER: 133.94,217.47 134.35,217.88 148.25,217.88 152.01,214.12 152.01,200.36 151.28,199.63 141.3,199.63 139.4,197.73 124.52,197.73 120.25,202 120.25,218.36 117.46,221.15 75.64,221.15 58.23,238.56 58.23,296.65 81.44,319.87 97.72,319.87 102.73,324.87 102.73,343.46 103.78,344.51 115.25,344.51 115.86,343.9 115.86,339.42 115.31,338.88 111.65,338.88 111.16,338.39 111.16,321.38 101.28,311.5 85.26,311.5 69.25,295.48 69.25,242.88 79.65,232.47 100.43,232.47 104.8,228.1 124.12,228.1 125.44,226.79 125.44,205.42 126.68,204.18 143.24,204.18 144.72,205.66 144.72,208.81 143.85,209.68 139.43,209.68 138.94,209.19 135.14,209.19 133.94,210.39
CSDPS425P9 on L20_SIGNAL: 139.71,198.74 139.71,134.43 129.74,124.46 93.54,124.46 86.89,131.11 86.89,155.39 69.81,172.48 69.81,275.63 79.49,285.31 79.49,330.47 87.78,338.77 110.41,338.77 111.24,339.6 111.24,343.93 110.62,344.55 81.43,344.55 71.41,334.54 71.41,304.6 57.3,290.48 57.3,203.99 44.01,190.71 38.82,190.71 37.11,189 37.11,148.01 70.75,114.37 131.33,114.37 164.54,147.58 164.54,193.34 156.93,200.95 141.92,200.95
CSDPS425P11 on L12_USER: 118.34,192.98 139.73,192.98 140.24,193.49 140.24,199.63 149.86,209.25 149.86,221.63 139.31,232.19 139.31,234.97 137.08,237.2 109.91,237.2 84.92,212.21 55.84,212.21 50.94,207.31 50.94,178.79 52.31,177.41 59.62,177.41 60.36,178.15 60.36,182.49 79.06,201.2 110.12,201.2
CSDPS425P11 on L18_POWER: 117.93,211.01 117.73,210.81 115.68,210.81 114.77,211.73 108.9,211.73 108.31,212.31 91.22,212.31 82,221.53 82,298.75 105.52,322.26 105.52,338.06 104.6,338.99 103.56,338.99 102.82,339.73 102.82,343.78 103.76,344.72 112.94,344.72 113.84,343.82 113.84,318.8 89.21,294.18 89.21,227.82 94.35,222.68 115.94,222.68 117.93,220.7
CSDPS425P13 on L16_POWER: 129.45,206.8 129.45,188.27 123.44,182.26 79.05,182.26 56.23,205.08 56.23,306.12 88.77,338.67 100.42,338.67 101.01,339.26 101.01,343.86 100.27,344.6 85.24,344.6 48.5,307.86 48.5,203.45 77.19,174.75 127.68,174.75 133.88,180.94 133.88,206.93 133.58,207.23 129.87,207.23
CSDPS425P15 on L11_POWER: 117.91,219.05 117.91,214.46 117.22,213.77 62.41,213.77 57.09,219.09 57.09,223.7 50.41,230.38 50.41,302.46 70.35,322.4 70.35,328.8 86.15,344.6 94.71,344.6 95.75,343.56 95.75,339.67 94.86,338.77 88.76,338.77 77.34,327.35 77.34,320.71 56.48,299.85 56.48,236.73 74.77,218.44 100.79,218.44 102.48,220.12 116.84,220.12
CSDPS429P1 on L09_POWER: 227.13,217.08 229.38,219.33 229.38,227.37 234.38,232.37 234.38,264.03 231.21,267.2 168.28,267.2 158.58,257.5 158.58,191.06 155.07,187.55 68.39,187.55 48.2,207.74 48.2,228.11 34.05,242.26 34.05,292.79 66.09,324.83 66.09,344.13 63.13,347.09 55.32,347.09 54.64,346.41 54.64,339.81 55.52,338.94 58.04,338.94 58.28,338.7 58.28,326.89 24.97,293.58 24.97,241.3 25.54,240.73 27.58,240.73 42.4,225.9 42.4,202.32 62.44,182.28 161.25,182.28 167.53,188.56 167.53,248.55 175.28,256.3 198.6,256.3 211,243.91 211,239.5 213,237.5 213,220.62 213.93,219.69 213.93,218.28 215.12,217.08
CSDPS429P5 on L20_SIGNAL: 203.34,132.64 156.85,132.64 136.32,112.11 69.56,112.11 32.73,148.94 32.73,188.85 37.65,193.77 41.51,193.77 52.33,204.59 52.33,297.47 58.6,303.73 58.6,344.06 58.09,344.58 44.93,344.58 44.31,343.96 44.31,339.53 45.01,338.84 46.44,338.84 46.99,338.29 46.99,310.51 41.44,304.95 41.44,208 34.75,201.31 29.88,201.31 26.3,197.73 26.3,147.38 67.81,105.87 138.6,105.87 154.96,122.24 202.66,122.24 204.81,124.39 204.81,131.18
CSDPS429P7 on L11_POWER: 213.94,217.47 214.35,217.88 228.25,217.88 232.01,214.12 232.01,200.36 231.28,199.63 221.3,199.63 219.4,197.73 204.52,197.73 200.21,202.04 200.21,218.41 197.46,221.15 181.48,221.15 172.35,212.02 172.35,182.03 153.96,163.64 43.29,163.64 25.04,181.89 25.04,319.59 29.06,323.61 29.06,344 29.64,344.58 41.76,344.58 42.59,343.75 42.59,339.67 41.91,339 35.77,339 34.87,338.1 34.87,318.93 36.01,317.79 36.01,292.63 36.02,292.58 36.02,205.53 47.8,193.75 47.8,188.29 61.07,175.01 155.13,175.01 166.9,186.78 166.9,223.66 174.56,231.32 182.35,231.32 185.56,228.1 203.69,228.1 205.21,226.58 205.21,205.65 206.68,204.18 223.24,204.18 224.72,205.66 224.72,208.81 223.85,209.68 219.43,209.68 218.94,209.19 215.14,209.19 213.94,210.39
CSDPS429P9 on L20_SIGNAL: 234.11,159.68 243.68,150.1 243.68,120.52 223.03,99.87 143.98,99.87 136.12,92.01 74.83,92.01 18.83,148 18.83,200.49 24.46,206.12 32.82,206.12 36.16,209.47 36.16,295.95 27.27,304.85 27.27,338.13 28.01,338.88 36.79,338.88 37.54,339.62 37.54,344.02 36.98,344.58 17.81,344.58 16.98,343.75 16.98,214.79 7.38,205.19 7.38,149.01 73.48,82.91 150.28,82.91 160.92,93.55 259.88,93.55 280.08,113.75 280.08,204.37 272.73,211.71 235.63,211.71 234.11,210.19
CSDPS429P11 on L12_USER: 197.42,192.73 219.03,192.73 220.3,194 220.3,199.75 236.54,215.99 248.25,215.99 251.36,212.88 251.36,198.8 251.85,198.3 260.25,198.3 260.78,198.83 260.78,236.03 256.92,239.9 223.2,239.9 220.52,237.22 196.94,237.22 194.99,235.27 194.99,195.16
CSDPS429P11 on L18_POWER: 197.93,211.51 197.5,211.09 193.93,211.09 193.53,211.49 189.9,211.49 188.83,212.57 182.82,212.57 176.2,205.95 176.2,181.23 149.81,154.83 116.6,154.83 114.43,157 43.36,157 32.53,167.83 32.53,290.72 31.77,291.48 31.77,338.87 31.57,339.07 30.09,339.07 29.35,339.8 29.35,343.89 29.99,344.52 38.94,344.52 40.06,343.4 40.06,200.93 42.2,198.78 42.2,170.59 47.5,165.29 145.43,165.29 167.14,187 167.14,213.54 176.27,222.68 195.94,222.68 197.93,220.7
CSDPS429P13 on L16_POWER: 209.45,206.8 209.45,190.97 175.93,157.45 48.7,157.45 28.58,177.57 28.58,188.72 23.03,194.27 23.03,292.62 22.18,293.47 22.18,338.09 23.06,338.97 26.25,338.97 27.08,339.79 27.08,343.93 26.42,344.59 14.69,344.59 12.68,342.58 12.68,325.35 15.63,322.4 15.63,172.79 40.39,148.02 177.31,148.02 213.88,184.59 213.88,206.93 213.58,207.23 209.87,207.23
CSDPS429P15 on L11_POWER: 197.91,219.05 197.91,214.46 197.22,213.77 184.04,213.77 180.08,209.81 180.08,169.97 161.04,150.93 28.66,150.93 15.27,164.33 15.27,317.75 9.05,323.97 9.05,341.88 11.84,344.67 21.44,344.67 22.21,343.9 22.21,340.31 20.62,338.72 17.74,338.72 17.11,338.08 17.11,327.09 23.71,320.49 23.71,177.64 40.93,160.42 156.66,160.42 174.17,177.93 174.17,211.82 182.48,220.12 196.84,220.12
UDBGND on L14_POWER: 5.98,24.94 5.98,289.71 9.09,292.82 16.82,292.82 18.47,291.17 18.47,161.78 25.33,154.92 25.33,134.78 58.01,102.1 58.01,34.62 62.66,29.96 228.42,29.96 232.8,34.34 232.8,88.97 252.1,108.27 252.1,307.71 233.96,325.85 233.96,398.55 232.2,400.32 88.17,400.32 86.33,402.15 86.33,420.05 90.32,424.03 207.88,424.03 211.66,420.26 276.84,420.26 284.11,412.99 284.11,11.89 279.74,7.51 166.87,7.51 162.81,11.57 19.35,11.57
UT1_UP5V on L12_USER: 156.96,1.78 156.12,2.68 155.21,3.5 154.23,4.23 153.19,4.87 152.1,5.43 150.96,5.88 149.79,6.24 148.6,6.49 147.38,6.64 146.16,6.68 144.94,6.61 143.73,6.44 142.54,6.16 141.38,5.78 140.25,5.3 139.17,4.72 138.15,4.05 137.19,3.3 136.3,2.46 135.48,1.55 135.08,1.02 1.02,1.02 1.02,428.24 61.42,428.24 72.66,422.59 83.9,428.24 208.74,428.24 219.98,422.59 231.22,428.24 291.62,428.24 291.62,1.02 157.55,1.02

Small or netless copper shapes (teardrops, artwork), in the pictures only: 1 on L03_SIGNAL

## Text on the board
Ref Des/Silkscreen Bottom: 133 | 134 | 137 | 141 | 138 | 142 | 139 | 140 | 135 | 136 | 74 | 73 | 88 | 84 | 87 | 83 | 80 | 79 | 86 | 76 | 85 | 75 | 82 | 81 | 132 | 131 | 130 | 129 | 127 | 126 | 125 | 124 | 123 | 122 | 121 | 120 | 117 | 116 | 115 | 114 | 113 | 112 | 103 | 102 | 101 | 100 | 99 | 98 | 96 | 95 | 94 | 93 | 92 | 91 | 90 | 89 | 9.HPD | 8.AGMODE_SYNC | 7.PWMI | 6.FAIL_FLAGO | 5.B_EIO | 4.F_EIO | 1.TEST | 3.STV_IN | 2.AGMODE
Ref Des/Silkscreen Top: 138 | 137 | 134 | 143 | 133 | 142 | 141 | 140 | 136 | 135 | 73 | 87 | 88 | 74 | 79 | 83 | 80 | 84 | 75 | 76 | 85 | 86 | 81 | 82 | 176 | 132 | 1 | SITE0 | HX8880 | 44 | 89 | 45 | 131 | 130 | 129 | 127 | 126 | 125 | 124 | 123 | 122 | 121 | 120 | 117 | 116 | 115 | 114 | 113 | 112 | 103 | 102 | 101 | 100 | 99 | 98 | 96 | 95 | 94 | 93 | 92 | 91 | 90 | 2.I2C_SDA | 1.I2C_SCL | 4.GND | 3.NC | Note:Component under socket | Group 3 | Group 8 | Group 1 | Group 2
User.5: NPTH1.62MMX4 | M3X4 | (0,0) | M4X4 | UNIT:MM | PCB Thickness:4.48MM | Group 8 | Group 3 | Group 2 | Group 1
User.17: 0.5 MIN | dia7
User.23: HEIGHT:1.4MM | HEIGHT:0.9MM | HEIGHT:1.91MM | HEIGHT:2.64MM | HEIGHT:9.5MM | UNIT:MM
User.24: HEIGHT:1.27MM | HEIGHT:10 MM | HEIGHT:9.6MM | HEIGHT:5.6MM | HEIGHT:0.9MM | HEIGHT:9 MM | HEIGHT:0.6MM | HEIGHT:8.6MM
User.45: FIGURE | SIZE | 12.0 | 12.1 | 12.11 | 14.0 | 14.01 | 28.0 | 40.0 | 41.0 | 169.0 | 252.0 | 64.0 | 126.0 | DRILL CHART: TOP to BOTTOM | ALL UNITS ARE IN MILS | TOLERANCE | +2.0/-2.0 | +3.0/-1.0 | +3.0/-0.0 | +2.0/-0.0 | +3.0/-3.0 | PLATED | NON-PLATED | QTY | 1104 | 1254 | 40 | 8 | 16 | 20 | 1564 | 970 | 4 | 36 | 336 | 18
